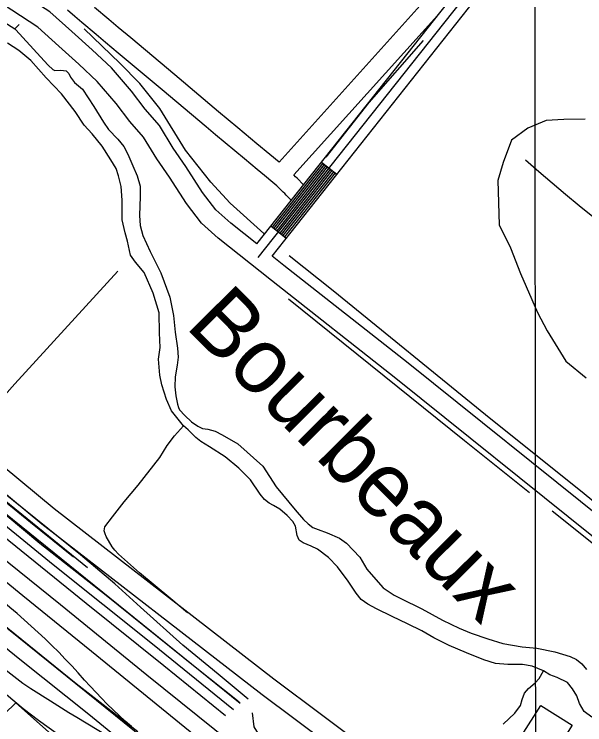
# Model space of a CAD drawing. Extents: x 3297753 to 3335611, y 652252 to 677623.
# Drawn here: x 3311584 to 3312458, y 664328 to 665417 of the extents above; entities that cross this region are included whole.
import ezdxf

# ---------------------------------------------------------------- set-up
doc = ezdxf.new("R2010")
doc.units = 0
for name, color, linetype in [('V-BLDG-OTLN', 7, 'Continuous'), ('V-GRID-MAJR', 7, 'Continuous'), ('V-RAIL-TRAK', 7, 'Continuous'), ('V-RIVR-IDEN', 7, 'Continuous'), ('V-ROAD-CNTR', 7, 'Continuous'), ('V-SITE-OTLN', 7, 'Continuous'), ('V-TOPO-SHOR', 7, 'Continuous')]:
    doc.layers.add(name, color=color, linetype=linetype)

msp = doc.modelspace()

# ---------------------------------------------------------------- linework, layer by layer
at = {"layer": 'V-BLDG-OTLN'}
msp.add_lwpolyline([(3312390.5, 664357.5), (3312438.6, 664327.2), (3312409.1, 664280.6), (3312361.1, 664310.9)], close=True, dxfattribs=at)
at = {"layer": 'V-GRID-MAJR'}
msp.add_spline([(3312388.7, 657641.3), (3312386, 660669), (3312380.7, 666730.4), (3312375.4, 672791.8), (3312372.8, 675825.6)], degree=3, dxfattribs=at)
at = {"layer": 'V-RAIL-TRAK'}
for points in [[(3311773.2, 664317), (3311678.8, 664390.7), (3311563.6, 664484.4), (3311470.2, 664557), (3311355, 664652.5), (3311242.5, 664741.8), (3311124.6, 664836.7), (3311022.1, 664918.1), (3310927.2, 664996.5), (3310828.8, 665077.1), (3310739.8, 665150.2), (3310627.3, 665239.9), (3310549.2, 665303), (3310467, 665366.4), (3310418.6, 665407.1), (3310380.2, 665439.5), (3310337.7, 665470.9)], [(3311952.8, 664236.2), (3311845.1, 664323.9), (3311702.3, 664440.1), (3311597.1, 664525.8), (3311519.9, 664588.5), (3311404.5, 664681.1), (3311290.7, 664774.2), (3311177.9, 664864.8), (3311067.6, 664953.9), (3310962.4, 665038.6), (3310844.6, 665129.7), (3310757.2, 665198.6), (3310673.4, 665266.5), (3310620.1, 665306.9), (3310575.7, 665339.3), (3310546, 665358.9), (3310499.3, 665385.9)], [(3311768.5, 664286), (3311698.4, 664343.8), (3311592.7, 664428.3), (3311483.4, 664516.3), (3311351.1, 664622.6), (3311245.8, 664708.9), (3311114.9, 664811.7), (3310998.4, 664905.8), (3310878.2, 665002.1), (3310740.4, 665113.7), (3310665.1, 665175.5), (3310620.3, 665212.2), (3310541.2, 665276.1), (3310476.1, 665325.3)], [(3311917.2, 664299.4), (3311787.1, 664403.8), (3311655, 664511.7), (3311511.7, 664626.9), (3311363.8, 664747.1), (3311235.3, 664849.5), (3311069.6, 664983.9), (3310870.4, 665143.9), (3310800.4, 665197.1), (3310731.9, 665248.2), (3310727.2, 665251.6), (3310675.1, 665284.5), (3310644.5, 665300.3)], [(3311919.4, 664197.2), (3311864, 664230.7), (3311843, 664242.8), (3311805, 664264.6), (3311768.5, 664286), (3311742, 664301.5), (3311679.7, 664339.1), (3311667.7, 664346.3), (3311639.8, 664364.2), (3311609.6, 664382.9), (3311597.4, 664391.2), (3311544.2, 664432.3), (3311418.1, 664534.7), (3311305.2, 664624.9), (3311204.5, 664706.8), (3311111.4, 664782.5), (3311024.7, 664853), (3310952.4, 664911.2), (3310828.2, 665011.4), (3310739.7, 665080.1), (3310651.7, 665151.5), (3310607, 665188.3)], [(3310973.7, 665111.9), (3311035.9, 665072.2), (3311098.1, 665032.6), (3311160.2, 664992.8), (3311171.3, 664986.1), (3311182.4, 664979.3), (3311193.3, 664972.2), (3311204, 664965), (3311214.6, 664957.6), (3311225.1, 664949.9), (3311235.5, 664942.1), (3311245.7, 664934.1), (3311255.8, 664926), (3311265.7, 664917.6), (3311275.5, 664909.1), (3311285.1, 664900.4), (3311391.3, 664814.7), (3311516.8, 664713.2), (3311608.8, 664638.4), (3311674.9, 664585.2)], [(3311907.4, 664341.5), (3311813.4, 664418.3), (3311694, 664513.8), (3311575.6, 664609.8), (3311465.8, 664699), (3311329.6, 664808.8), (3311210.2, 664904.8), (3311173.6, 664933.4), (3311167.6, 664937.3), (3311161.6, 664941.4), (3311155.8, 664945.6), (3311150.1, 664950.1), (3311144.5, 664954.7), (3311139.1, 664959.4), (3311133.8, 664964.4), (3311128.7, 664969.4), (3311123.7, 664974.7), (3311118.9, 664980.1), (3311114.2, 664985.6), (3311109.7, 664991.3), (3311105.4, 664997.1), (3311068.8, 665035.6)], [(3311098.1, 665032.6), (3311158.6, 664983.3), (3311238.3, 664919.3), (3311348.1, 664829.6), (3311469.5, 664734.7), (3311623, 664606.5), (3311724.6, 664526.8), (3311861.3, 664417), (3311928.4, 664363.3)], [(3311522.4, 664672.3), (3311643.4, 664573.8), (3311795.8, 664452.1), (3311919.8, 664351.2)], [(3311763.5, 664325.3), (3311754.1, 664333.6), (3311744.7, 664342.2), (3311735.5, 664350.9), (3311726.4, 664359.7), (3311717.5, 664368.7), (3311709.3, 664377.3), (3311700.1, 664387.1), (3311691.7, 664396.5), (3311682, 664407.4), (3311672.2, 664418.1), (3311662.2, 664428.6), (3311652.1, 664439.1), (3311641.8, 664449.3), (3311631.4, 664459.5), (3311620.9, 664469.5), (3311610.2, 664479.3), (3311599.4, 664489), (3311588.5, 664498.6), (3311577.4, 664508), (3311566.2, 664517.3)]]:
    msp.add_lwpolyline(points, dxfattribs=at)
at = {"layer": 'V-ROAD-CNTR'}
for p, q in [((3312054.7, 665190.7), (3312078.2, 665172.1)), ((3311977.1, 665092.7), (3312000.7, 665074.1))]:
    msp.add_line(p, q, dxfattribs=at)
for points in [[(3311955.5, 665065.3), (3312290.8, 665489.1), (3312311.5, 665592), (3312335.9, 665643.7), (3312374.1, 665686.5), (3312440, 665748.1), (3312491, 665786.3), (3312515.4, 665800.7), (3312538.9, 665811.5), (3312565, 665815.1), (3312870.8, 665811.2), (3312902.2, 665785), (3312919.9, 665754.5), (3312934.6, 665717.6), (3312945.1, 665681.7), (3312949.3, 665644), (3312945.5, 665601.1), (3312940.6, 665563.6), (3312927.8, 665534.1)], [(3311957.9, 665044.2), (3312304.8, 665482.6), (3312325.9, 665587.2), (3312348.6, 665635.3), (3312384.8, 665676), (3312449.6, 665736.6), (3312499.3, 665773.8)], [(3310084.5, 665676.5), (3311397.6, 664617.7), (3313130.1, 663219.2), (3314152.4, 662384.5)], [(3310478.9, 665593.9), (3310541.5, 665562.2), (3310583.5, 665545.9), (3310622.7, 665518.4), (3310656.7, 665499.9), (3310689.3, 665473.2), (3310704.3, 665452.3), (3310730.2, 665414.8), (3310753.1, 665371.7), (3310773.1, 665335.3), (3310791.8, 665309.2), (3310839, 665273.3), (3310871.3, 665237.9), (3310923.7, 665214.2), (3310963, 665191.7), (3311019.1, 665147.9), (3311055.4, 665117.3), (3311063, 665117), (3311356.2, 664899), (3311645, 664659.5), (3311981.8, 664398.5), (3312132, 664286.2)], [(3310456.4, 665571.7), (3310529.2, 665534.8), (3310569.3, 665519.2), (3310606.9, 665492.8), (3310639.8, 665474.9), (3310667.2, 665452.5), (3310679.8, 665435), (3310704.5, 665399.1), (3310726.7, 665357.4), (3310747.7, 665319.3), (3310770, 665288), (3310818.7, 665251), (3310853.3, 665213.1), (3310910, 665187.4), (3310946.3, 665166.7), (3311000.2, 665124.6), (3311043.9, 665087.6), (3311052.6, 665087.4), (3311337.7, 664875.4), (3311626.2, 664636.1), (3311963.7, 664374.6), (3312113.4, 664262.7)], [(3311978.9, 665046.6), (3312318.8, 665476.1), (3312319, 665477.2)], [(3311955.5, 665065.3), (3311915.6, 665097), (3311892.8, 665117.4), (3311872.3, 665144.1), (3311847.1, 665183.9), (3311827.6, 665211.8), (3311806.5, 665246.9), (3311784.4, 665271.7), (3311763.7, 665299.3), (3311732.8, 665335), (3311703.3, 665362.9), (3311672.4, 665390.8), (3311638.6, 665421.1), (3311603, 665444.6)], [(3312471.5, 664615.7), (3312168.6, 664858.9), (3311978.3, 665008.8), (3311896.2, 665074.1), (3311870.7, 665096.9), (3311847.7, 665126.9), (3311822.1, 665167.3), (3311802.4, 665195.5), (3311782.2, 665229), (3311761.2, 665252.6), (3311740.3, 665280.4), (3311711.1, 665314.3), (3311683, 665340.8), (3311652.3, 665368.5), (3311620.2, 665397.3), (3311567, 665432.3)], [(3311989.6, 665190.5), (3311975.4, 665202.4), (3311955.8, 665218.7), (3311926.4, 665243.1), (3311911.7, 665255.3), (3311897.1, 665267.5), (3311829.8, 665324.1), (3311762.4, 665380.8), (3311743.2, 665397), (3311728.7, 665409.2), (3311707.1, 665427.5)], [(3311989.6, 665190.5), (3312210.2, 665435.8)], [(3312008.3, 665132.1), (3312000.8, 665139.9), (3311998.3, 665142.5), (3311996, 665144.7), (3311994.1, 665146.6), (3311990.6, 665149.9), (3311988, 665152.4), (3311986.1, 665154.2), (3311983.1, 665156.8), (3311980, 665159.4), (3311967.3, 665170.1), (3311956.2, 665179.4), (3311936.6, 665195.6), (3311907.2, 665220), (3311892.5, 665232.3), (3311877.8, 665244.5), (3311810.5, 665301.2), (3311743.1, 665357.8), (3311723.8, 665374.1), (3311709.4, 665386.3), (3311687.7, 665404.6), (3311676.9, 665413.9), (3311665.8, 665423.3)], [(3312012.2, 665170.8), (3312236.8, 665420.5)], [(3312458.7, 665256.2), (3312425.7, 665255.8), (3312398.6, 665254.3), (3312370.8, 665242.8), (3312345.5, 665224.4), (3312333.2, 665190.1), (3312324.8, 665162.3), (3312326.8, 665094.3), (3312344, 665059), (3312359.4, 665019.9), (3312385.5, 664960.1), (3312400.3, 664932.1), (3312429.1, 664885.5), (3312460.3, 664859.6)], [(3311979.5, 665090.8), (3312057.1, 665188.9)], [(3312470.2, 665106.5), (3312449.4, 665123.6), (3312428.6, 665140.9), (3312407.9, 665158.3), (3312387.4, 665175.8), (3312367, 665193.4)], [(3311981.9, 665089), (3312059.4, 665187)], [(3311984.2, 665087.1), (3312061.8, 665185.1)], [(3311986.6, 665085.3), (3312064.1, 665183.3)], [(3311988.9, 665083.4), (3312066.5, 665181.4)], [(3311991.3, 665081.5), (3312068.8, 665179.6)], [(3311993.6, 665079.7), (3312071.2, 665177.7)], [(3311996, 665077.8), (3312073.5, 665175.8)], [(3311998.3, 665075.9), (3312075.9, 665174)], [(3312027.2, 665155.9), (3312017.2, 665166), (3312015, 665168.1), (3312012.2, 665170.8)], [(3312731.9, 664449), (3312490.2, 664639.2), (3312187.3, 664882.4), (3311996.9, 665032.3), (3311978.9, 665046.6)], [(3311125.8, 665010.3), (3311482.4, 664722.8), (3311930.2, 664361.3)], [(3311224.1, 664950.3), (3311491.8, 664734.5), (3311696.5, 664569.2)]]:
    msp.add_lwpolyline(points, dxfattribs=at)
at = {"layer": 'V-SITE-OTLN'}
msp.add_lwpolyline([(3309889, 665592.8), (3310756.4, 664885.2), (3310905.3, 664756.3), (3311028.2, 664650), (3311498.3, 664276.5), (3311586.4, 664361.5), (3312077.6, 663925), (3312095.2, 663905.1), (3312124.8, 663853.6), (3312131.2, 663813.3), (3312121.9, 663669), (3312586.6, 663269.5), (3312820.3, 663057.3), (3312864.4, 663017.2), (3313074.7, 663222.3), (3313449.7, 662841.6), (3313794.7, 662535.5), (3313961.1, 662402.5), (3314004.4, 662400.3), (3314238.5, 662553.8), (3314592.2, 662807.3)], dxfattribs=at)
at = {"layer": 'V-TOPO-SHOR'}
for p, q in [((3311591.6, 665401.5), (3311584.8, 665394.8)), ((3312545.2, 664545.6), (3312407.9, 664655.4))]:
    msp.add_line(p, q, dxfattribs=at)
for points in [[(3311554.9, 665414), (3311584.8, 665394.8), (3311586.7, 665393.5), (3311624.5, 665352.1)], [(3311966.4, 665081.2), (3311914.8, 665127.4), (3311885.4, 665159.8), (3311846.4, 665208.8), (3311806.8, 665272.5), (3311776.6, 665310.9), (3311745.6, 665342), (3311691.3, 665394.7)], [(3312062, 665198.2), (3312127.6, 665281.7), (3312210.8, 665376.8)], [(3311609.5, 665346.5), (3311590.9, 665361.4), (3311573.6, 665372.7)], [(3311624.5, 665352.1), (3311636.2, 665339.3), (3311643.1, 665332.6), (3311646.4, 665331.2), (3311655.5, 665331.4), (3311663.5, 665330.3), (3311667.7, 665326.2), (3311670.2, 665320.9), (3311676.2, 665312.5), (3311688.8, 665302.6), (3311705.7, 665276), (3311720.6, 665252), (3311728.4, 665240.6), (3311742.9, 665225.7)], [(3311805.2, 664888.7), (3311807.3, 664906.2), (3311806.7, 664928.6), (3311805.9, 664959.6), (3311796.6, 664989.6), (3311783.1, 665021.3), (3311769.8, 665037.4), (3311762.3, 665047.9), (3311757.5, 665069.1), (3311753.8, 665082.1), (3311749.3, 665101.8), (3311749.4, 665132.2), (3311747.9, 665152.9), (3311743.8, 665169.4), (3311740.1, 665180.6), (3311732.2, 665193.8), (3311718.9, 665214.8), (3311703.5, 665234.1), (3311690.9, 665247.2), (3311677.3, 665268.3), (3311656.2, 665295.1), (3311632.8, 665319.9), (3311609.5, 665346.5)], [(3311742.9, 665225.7), (3311751.9, 665214.3), (3311758, 665202.6), (3311765.6, 665184.7), (3311772.4, 665169.4), (3311777.1, 665153.8), (3311776.7, 665137.9), (3311776, 665108.9), (3311777.1, 665093.2), (3311780.9, 665077.9), (3311792.2, 665053.6), (3311808.4, 665020.7), (3311822.2, 664983.4), (3311828, 664955.4), (3311830.5, 664929.7), (3311834.1, 664905.3), (3311834.9, 664891.4), (3311833.6, 664879.3), (3311830.3, 664861.5), (3311830, 664846.1), (3311831.7, 664832.5), (3311834.2, 664819.6), (3311835.5, 664814.6), (3311837.3, 664810.8), (3311845.1, 664802.3), (3311855.3, 664792.4), (3311865.5, 664785.8), (3311872.6, 664782.3), (3311880.6, 664781.3), (3311891.9, 664777.9), (3311902.6, 664772.7), (3311926.5, 664758.6), (3311964.8, 664724.6), (3311985.4, 664693), (3312014.3, 664657.7), (3312027, 664642.8), (3312034.2, 664635.9), (3312041.4, 664630.4), (3312049.4, 664627.2), (3312063.3, 664622.4), (3312082.1, 664614.1), (3312093.1, 664606.6), (3312113.3, 664585.1), (3312123.9, 664566.6), (3312137.7, 664550.6), (3312148.9, 664537.7), (3312165.9, 664526.8), (3312176.3, 664521.6), (3312208.2, 664505.5), (3312239.8, 664488.6), (3312265.7, 664476.3), (3312283.8, 664468.6), (3312309.4, 664459.5), (3312332.2, 664452.8), (3312362.2, 664447.6), (3312384.4, 664445.6), (3312412.2, 664439.8), (3312435.4, 664432.5), (3312445.5, 664427.9), (3312453.3, 664421.2), (3312460.8, 664412.5)], [(3311942.1, 664367), (3311896.6, 664405.6), (3311842.3, 664450.2), (3311777.3, 664508.2), (3311738, 664544.2), (3311685.6, 664588.3), (3311567.2, 664683.9), (3311454, 664774.6), (3311339.1, 664866.1), (3311167.2, 665002.3), (3311121.6, 665030.9), (3311081.1, 665058.2)], [(3312706.2, 664480.2), (3312572.8, 664586.3), (3312457.1, 664681.8), (3312306, 664803.2), (3312072.6, 664993), (3312004.9, 665046.8)], [(3311742.7, 665023.5), (3311693.9, 664969.8), (3311584.7, 664850.7), (3311521.5, 664779.6), (3311514.1, 664776.6), (3311504, 664780.3), (3311464.6, 664809.5), (3311333.2, 664915.6)], [(3312373.4, 664683.5), (3312273.5, 664763.1), (3312088.1, 664913.1), (3312004.3, 664980.6)], [(3312468.9, 664339.4), (3312457.2, 664348.4), (3312449.9, 664360.4), (3312445.9, 664372.2), (3312439.2, 664383.3), (3312431.7, 664392.7), (3312415.9, 664400.4), (3312404.6, 664404.7), (3312394.8, 664410.7), (3312377.5, 664417.8), (3312362.7, 664420.6), (3312340.2, 664420.5), (3312321.3, 664422), (3312303.2, 664427.3), (3312276.7, 664438.2), (3312250, 664449.3), (3312226.7, 664461.3), (3312208.5, 664472), (3312186.2, 664482.9), (3312162.7, 664494), (3312138.9, 664505.5), (3312125.7, 664512.7), (3312115.6, 664519.9), (3312108, 664529.8), (3312095.6, 664548.3), (3312079.3, 664569.9), (3312065.5, 664584.2), (3312048.5, 664597.2), (3312038.7, 664601.8), (3312026.5, 664606.9), (3312020.5, 664611.2), (3312017.4, 664618.3), (3312015.1, 664632.4), (3312010.6, 664639.8), (3312001.9, 664648.8), (3311991.1, 664658.7), (3311981.3, 664664.1), (3311974.7, 664667.6), (3311967.5, 664673.1), (3311960.9, 664681.5), (3311945.8, 664703.5), (3311927.8, 664721.2), (3311907.1, 664738.6), (3311882.9, 664753.9), (3311870.1, 664762.3), (3311862, 664768.4), (3311850.6, 664780.3), (3311843.4, 664786.2), (3311825, 664809.5), (3311817.1, 664826.8), (3311809.9, 664849.2), (3311806.8, 664863.9), (3311805.2, 664888.7)], [(3311734, 664601), (3311724.6, 664616.7), (3311723.1, 664620.5), (3311721.9, 664625.5), (3311722.9, 664631.3), (3311734.5, 664646.9), (3311752.6, 664669.7), (3311773.6, 664695.1), (3311807, 664737.9), (3311818.2, 664755.9), (3311829.7, 664771), (3311843.4, 664786.2)], [(3311849.2, 664499.7), (3311824.1, 664520.8), (3311775.8, 664561.1), (3311743.6, 664589.5), (3311738.3, 664595.5), (3311734, 664601)], [(3311670.3, 664299.1), (3311621.1, 664334.4), (3311597.9, 664352.3), (3311572.4, 664374.1), (3311530.3, 664408.4), (3311470.9, 664455.2), (3311422.1, 664494.5), (3311358.5, 664544.5), (3311303.5, 664590.3)], [(3312333, 664328.8), (3312350.7, 664346), (3312359.3, 664357.7), (3312361.9, 664366.8), (3312365.7, 664376.5), (3312371.7, 664383.7), (3312381.9, 664392.1), (3312387.9, 664398.9), (3312394.8, 664410.7)], [(3312712, 663799.3), (3312617.9, 663873.5), (3312540.4, 663934.1), (3312497.7, 663967.3), (3312473.4, 663985.4), (3312447.1, 664002.7), (3312405.1, 664026.3), (3312314.7, 664080), (3312260.1, 664111.5), (3312229.8, 664127.8), (3312205, 664142.4), (3312175.4, 664157.6), (3312094.5, 664204.1), (3312048.6, 664233.9), (3312010.9, 664264.6), (3311980.9, 664291.4), (3311958, 664314), (3311951.4, 664324.6), (3311948.8, 664346.4)]]:
    msp.add_lwpolyline(points, dxfattribs=at)

# ---------------------------------------------------------------- texts
at = {"layer": 'V-RIVR-IDEN'}
msp.add_text('Bourbeaux', height=100, rotation=314.8127, dxfattribs=at).set_placement((3311844.5, 664938.2))

doc.saveas('drawing.dxf')
